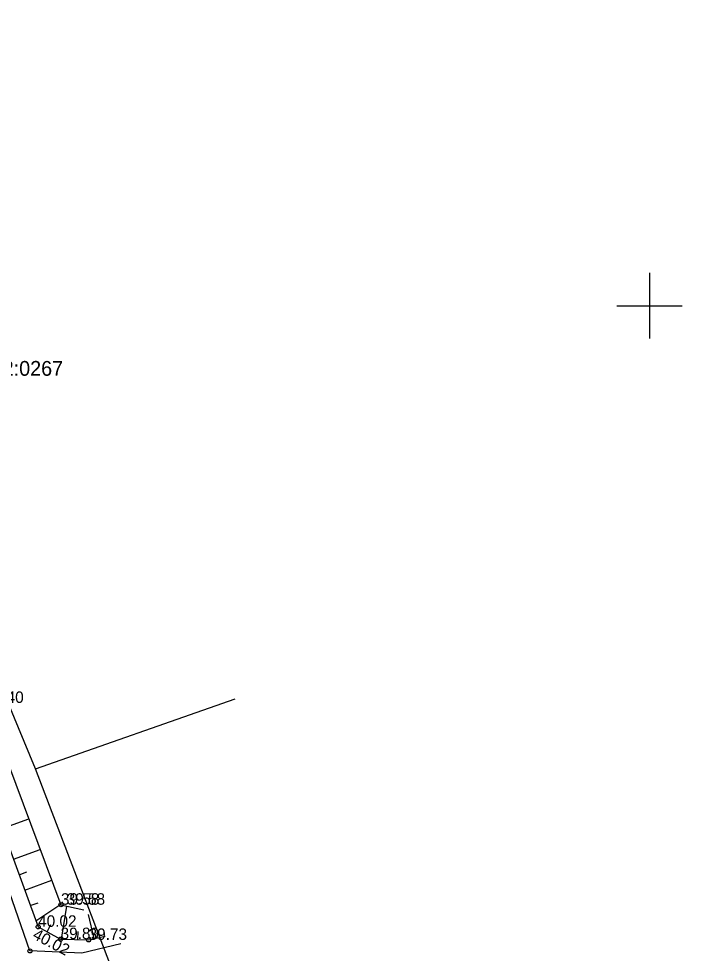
# Model space of a CAD drawing. Extents: x 627548 to 628052, y 6467984 to 6468802.
# Drawn here: x 627911.6 to 627952, y 6468260.5 to 6468317.5 of the extents above; entities that cross this region are included whole.
import ezdxf

# ---------------------------------------------------------------- set-up
doc = ezdxf.new("R2010")
doc.units = 0
for name, color, linetype in [('KORGUS-EH2000', 7, 'Continuous'), ('MOOTKORG-EH2000', 7, 'Continuous'), ('MOOTMPUNKT', 7, 'Continuous'), ('PIIR', 7, 'Continuous'), ('RELJEEF', 7, 'Continuous'), ('TEE', 7, 'Continuous'), ('VORK', 7, 'Continuous')]:
    doc.layers.add(name, color=color, linetype=linetype)

msp = doc.modelspace()

# ---------------------------------------------------------------- linework, layer by layer
at = {"layer": 'KORGUS-EH2000'}
msp.add_circle((627912.243, 6468260.69), 0.125, dxfattribs=at)
at = {"layer": 'MOOTMPUNKT'}
for centre in [(627914.133, 6468263.505), (627912.743, 6468262.16), (627914.112, 6468261.408), (627915.818, 6468261.36)]:
    msp.add_circle(centre, 0.125, dxfattribs=at)
at = {"layer": 'PIIR'}
for p, q in [((627912.59, 6468271.79), (627893.5, 6468317.49)), ((627912.59, 6468271.79), (627924.76, 6468276.055)), ((627943.46, 6468191.01), (627912.59, 6468271.79))]:
    msp.add_line(p, q, dxfattribs=at)
at = {"layer": 'RELJEEF'}
for p, q in [((627910.548, 6468268.151), (627912.168, 6468268.744)), ((627911.236, 6468266.273), (627912.871, 6468266.872)), ((627911.58, 6468265.334), (627912.05, 6468265.506)), ((627911.924, 6468264.395), (627913.573, 6468264.999)), ((627912.268, 6468263.456), (627912.738, 6468263.628)), ((627912.612, 6468262.517), (627914.12, 6468263.54)), ((627914.17, 6468261.406), (627914.502, 6468263.423)), ((627916.16, 6468261.439), (627915.821, 6468262.901)), ((627913.286, 6468261.862), (627913.527, 6468262.3)), ((627915.169, 6468261.378), (627915.184, 6468261.878))]:
    msp.add_line(p, q, dxfattribs=at)
for points in [[(627902.143, 6468298.82), (627901.144, 6468296.301), (627901.175, 6468294.123), (627908.047, 6468274.979), (627912.743, 6468262.16), (627914.112, 6468261.408), (627915.818, 6468261.36), (627916.836, 6468261.596)], [(627903.454, 6468298.207), (627902.726, 6468296.488), (627909.522, 6468275.801), (627914.133, 6468263.505), (627915.522, 6468263.197)]]:
    msp.add_lwpolyline(points, dxfattribs=at)
at = {"layer": 'TEE'}
msp.add_lwpolyline([(627917.783, 6468261.132), (627915.406, 6468260.556), (627912.243, 6468260.69), (627909.567, 6468268.305), (627905.673, 6468277.849), (627901.988, 6468287.172), (627899.253, 6468294.574), (627901.367, 6468298.21), (627903.149, 6468299.908)], dxfattribs=at)
at = {"layer": 'VORK'}
for p, q in [((627950, 6468302), (627950, 6468298)), ((627948, 6468300), (627952, 6468300))]:
    msp.add_line(p, q, dxfattribs=at)

# ---------------------------------------------------------------- texts
at = {"layer": 'KORGUS-EH2000'}
msp.add_text('39.58', height=0.7, dxfattribs=at).set_placement((627914.483, 6468263.505))
msp.add_text('40.02', height=0.7, rotation=332.2395, dxfattribs=at).set_placement((627912.353, 6468261.471))
at = {"layer": 'MOOTKORG-EH2000'}
for s, p in [('39.40', (627909.522, 6468275.801)), ('39.58', (627914.133, 6468263.505)), ('40.02', (627912.743, 6468262.16)), ('39.89', (627914.112, 6468261.408)), ('39.73', (627915.818, 6468261.36))]:
    msp.add_text(s, height=0.7, dxfattribs=at).set_placement(p)
at = {"layer": 'PIIR'}
msp.add_text('66601:002:0267', height=0.9, dxfattribs=at).set_placement((627905.565, 6468295.734))

doc.saveas('drawing.dxf')
